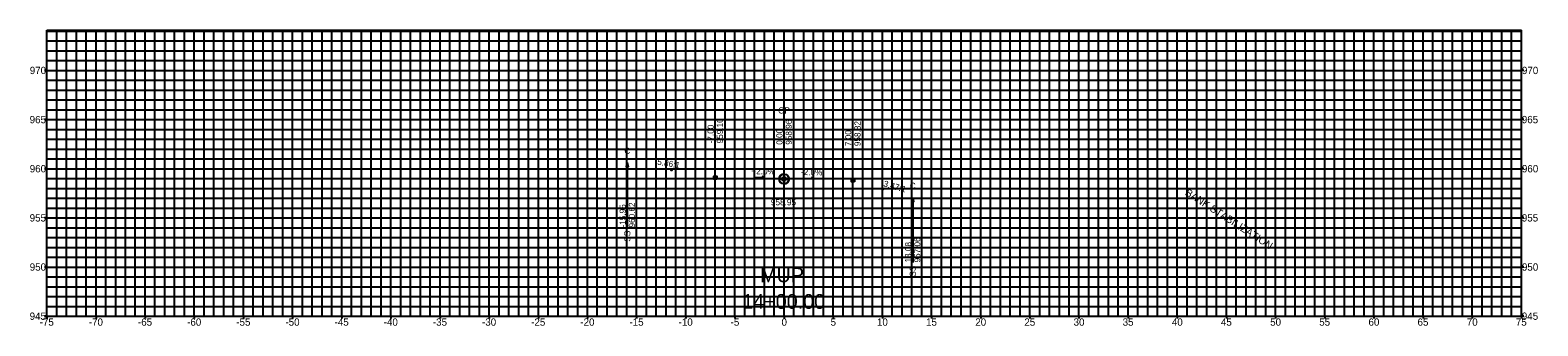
# Model space of a CAD drawing. Extents: x -77 to 77, y 944 to 974.
import ezdxf

# ---------------------------------------------------------------- set-up
doc = ezdxf.new("R2010")
doc.units = 0
for name, color, linetype in [('Default', 7, 'Continuous'), ('E_NCDOT_Terrain_Model_Boundary', 7, 'Continuous'), ('E_NCDOT_Terrain_Model_Breakline', 7, 'Continuous'), ('E_NCDOT_Terrain_Model_Contour_Imported', 7, 'Continuous'), ('E_NCDOT_Terrain_Model_Flow_Arrows', 7, 'Continuous'), ('E_NCDOT_Terrain_Model_Hole', 7, 'Continuous'), ('E_NCDOT_Terrain_Model_Island', 7, 'Continuous'), ('E_NCDOT_Terrain_Model_Points_High', 7, 'Continuous'), ('E_NCDOT_Terrain_Model_Points_Low', 7, 'Continuous'), ('P_NCDOT_XS_Label_Grade_Point', 7, 'Continuous'), ('P_NCDOT_XS_Label_Grading_Side_Slope', 7, 'Continuous'), ('P_NCDOT_XS_Leader_Line', 7, 'Continuous'), ('Prop XS Grade Point', 7, 'Continuous'), ('Prop XS Label Slope Superelevation', 7, 'Continuous')]:
    doc.layers.add(name, color=color, linetype=linetype)

msp = doc.modelspace()

# ---------------------------------------------------------------- linework, layer by layer
at = {"layer": 'Default'}
for p, q in [((-11.47, 959.86), (-11.47, 959.86)), ((10.04, 957.94), (10.04, 957.94))]:
    msp.add_line(p, q, dxfattribs=at)
at = {"layer": 'E_NCDOT_Terrain_Model_Boundary'}
for centre in [(-11.47, 959.86), (10.04, 957.94)]:
    msp.add_circle(centre, 0.05, dxfattribs=at)
at = {"layer": 'E_NCDOT_Terrain_Model_Flow_Arrows'}
for p, q in [((-75, 974.1), (75, 974.1)), ((-75, 945), (-75, 974.1)), ((75, 945), (75, 974.1)), ((-75, 945), (75, 945))]:
    msp.add_line(p, q, dxfattribs=at)
at = {"layer": 'E_NCDOT_Terrain_Model_Hole'}
for p, q in [((-70, 945), (-70, 974.1)), ((-60, 945), (-60, 974.1)), ((-50, 945), (-50, 974.1)), ((-40, 945), (-40, 974.1)), ((-30, 945), (-30, 974.1)), ((-20, 945), (-20, 974.1)), ((-10, 945), (-10, 974.1)), ((0, 945), (0, 974.1)), ((10, 945), (10, 974.1)), ((20, 945), (20, 974.1)), ((30, 945), (30, 974.1)), ((40, 945), (40, 974.1)), ((50, 945), (50, 974.1)), ((60, 945), (60, 974.1)), ((70, 945), (70, 974.1)), ((-75, 970), (75, 970)), ((-75, 960), (75, 960)), ((-75, 950), (75, 950))]:
    msp.add_line(p, q, dxfattribs=at)
at = {"layer": 'E_NCDOT_Terrain_Model_Points_High'}
for p, q in [((-75, 974), (75, 974)), ((-74, 945), (-74, 974.1)), ((-73, 945), (-73, 974.1)), ((-72, 945), (-72, 974.1)), ((-71, 945), (-71, 974.1)), ((-69, 945), (-69, 974.1)), ((-68, 945), (-68, 974.1)), ((-67, 945), (-67, 974.1)), ((-66, 945), (-66, 974.1)), ((-64, 945), (-64, 974.1)), ((-63, 945), (-63, 974.1)), ((-62, 945), (-62, 974.1)), ((-61, 945), (-61, 974.1)), ((-59, 945), (-59, 974.1)), ((-58, 945), (-58, 974.1)), ((-57, 945), (-57, 974.1)), ((-56, 945), (-56, 974.1)), ((-54, 945), (-54, 974.1)), ((-53, 945), (-53, 974.1)), ((-52, 945), (-52, 974.1)), ((-51, 945), (-51, 974.1)), ((-49, 945), (-49, 974.1)), ((-48, 945), (-48, 974.1)), ((-47, 945), (-47, 974.1)), ((-46, 945), (-46, 974.1)), ((-44, 945), (-44, 974.1)), ((-43, 945), (-43, 974.1)), ((-42, 945), (-42, 974.1)), ((-41, 945), (-41, 974.1)), ((-39, 945), (-39, 974.1)), ((-38, 945), (-38, 974.1)), ((-37, 945), (-37, 974.1)), ((-36, 945), (-36, 974.1)), ((-34, 945), (-34, 974.1)), ((-33, 945), (-33, 974.1)), ((-32, 945), (-32, 974.1)), ((-31, 945), (-31, 974.1)), ((-29, 945), (-29, 974.1)), ((-28, 945), (-28, 974.1)), ((-27, 945), (-27, 974.1)), ((-26, 945), (-26, 974.1)), ((-24, 945), (-24, 974.1)), ((-23, 945), (-23, 974.1)), ((-22, 945), (-22, 974.1)), ((-21, 945), (-21, 974.1)), ((-19, 945), (-19, 974.1)), ((-18, 945), (-18, 974.1)), ((-17, 945), (-17, 974.1)), ((-16, 945), (-16, 974.1)), ((-14, 945), (-14, 974.1)), ((-13, 945), (-13, 974.1)), ((-12, 945), (-12, 974.1)), ((-11, 945), (-11, 974.1)), ((-9, 945), (-9, 974.1)), ((-8, 945), (-8, 974.1)), ((-7, 945), (-7, 974.1)), ((-6, 945), (-6, 974.1)), ((-4, 945), (-4, 974.1)), ((-3, 945), (-3, 974.1)), ((-2, 945), (-2, 974.1)), ((-1, 945), (-1, 974.1)), ((1, 945), (1, 974.1)), ((2, 945), (2, 974.1)), ((3, 945), (3, 974.1)), ((4, 945), (4, 974.1)), ((6, 945), (6, 974.1)), ((7, 945), (7, 974.1)), ((8, 945), (8, 974.1)), ((9, 945), (9, 974.1)), ((11, 945), (11, 974.1)), ((12, 945), (12, 974.1)), ((13, 945), (13, 974.1)), ((14, 945), (14, 974.1)), ((16, 945), (16, 974.1)), ((17, 945), (17, 974.1)), ((18, 945), (18, 974.1)), ((19, 945), (19, 974.1)), ((21, 945), (21, 974.1)), ((22, 945), (22, 974.1)), ((23, 945), (23, 974.1)), ((24, 945), (24, 974.1)), ((26, 945), (26, 974.1)), ((27, 945), (27, 974.1)), ((28, 945), (28, 974.1)), ((29, 945), (29, 974.1)), ((31, 945), (31, 974.1)), ((32, 945), (32, 974.1)), ((33, 945), (33, 974.1)), ((34, 945), (34, 974.1)), ((36, 945), (36, 974.1)), ((37, 945), (37, 974.1)), ((38, 945), (38, 974.1)), ((39, 945), (39, 974.1)), ((41, 945), (41, 974.1)), ((42, 945), (42, 974.1)), ((43, 945), (43, 974.1)), ((44, 945), (44, 974.1)), ((46, 945), (46, 974.1)), ((47, 945), (47, 974.1)), ((48, 945), (48, 974.1)), ((49, 945), (49, 974.1)), ((51, 945), (51, 974.1)), ((52, 945), (52, 974.1)), ((53, 945), (53, 974.1)), ((54, 945), (54, 974.1)), ((56, 945), (56, 974.1)), ((57, 945), (57, 974.1)), ((58, 945), (58, 974.1)), ((59, 945), (59, 974.1)), ((61, 945), (61, 974.1)), ((62, 945), (62, 974.1)), ((63, 945), (63, 974.1)), ((64, 945), (64, 974.1)), ((66, 945), (66, 974.1)), ((67, 945), (67, 974.1)), ((68, 945), (68, 974.1)), ((69, 945), (69, 974.1)), ((71, 945), (71, 974.1)), ((72, 945), (72, 974.1)), ((73, 945), (73, 974.1)), ((74, 945), (74, 974.1)), ((-75, 973), (75, 973)), ((-75, 972), (75, 972)), ((-75, 971), (75, 971)), ((-75, 969), (75, 969)), ((-75, 968), (75, 968)), ((-75, 967), (75, 967)), ((-75, 966), (75, 966)), ((-75, 964), (75, 964)), ((-75, 963), (75, 963)), ((-75, 962), (75, 962)), ((-75, 961), (75, 961)), ((-75, 959), (75, 959)), ((-75, 958), (75, 958)), ((-75, 957), (75, 957)), ((-75, 956), (75, 956)), ((-75, 954), (75, 954)), ((-75, 953), (75, 953)), ((-75, 952), (75, 952)), ((-75, 951), (75, 951)), ((-75, 949), (75, 949)), ((-75, 948), (75, 948)), ((-75, 947), (75, 947)), ((-75, 946), (75, 946))]:
    msp.add_line(p, q, dxfattribs=at)
at = {"layer": 'E_NCDOT_Terrain_Model_Points_Low'}
for p, q in [((-70, 945), (-70, 974.1)), ((-65, 945), (-65, 974.1)), ((-60, 945), (-60, 974.1)), ((-55, 945), (-55, 974.1)), ((-50, 945), (-50, 974.1)), ((-45, 945), (-45, 974.1)), ((-40, 945), (-40, 974.1)), ((-35, 945), (-35, 974.1)), ((-30, 945), (-30, 974.1)), ((-25, 945), (-25, 974.1)), ((-20, 945), (-20, 974.1)), ((-15, 945), (-15, 974.1)), ((-10, 945), (-10, 974.1)), ((-5, 945), (-5, 974.1)), ((0, 945), (0, 974.1)), ((5, 945), (5, 974.1)), ((10, 945), (10, 974.1)), ((15, 945), (15, 974.1)), ((20, 945), (20, 974.1)), ((25, 945), (25, 974.1)), ((30, 945), (30, 974.1)), ((35, 945), (35, 974.1)), ((40, 945), (40, 974.1)), ((45, 945), (45, 974.1)), ((50, 945), (50, 974.1)), ((55, 945), (55, 974.1)), ((60, 945), (60, 974.1)), ((65, 945), (65, 974.1)), ((70, 945), (70, 974.1)), ((-75, 970), (-75.24, 970)), ((-75, 970), (75, 970)), ((75.24, 970), (75, 970)), ((-75, 965), (-75.24, 965)), ((-75, 965), (75, 965)), ((75.24, 965), (75, 965)), ((-75, 960), (-75.24, 960)), ((-75, 960), (75, 960)), ((75.24, 960), (75, 960)), ((-75, 955), (-75.24, 955)), ((-75, 955), (75, 955)), ((75.24, 955), (75, 955)), ((-75, 950), (-75.24, 950)), ((-75, 950), (75, 950)), ((75.24, 950), (75, 950)), ((-75, 945), (-75.24, 945)), ((-75, 945), (-75, 944.76)), ((-70, 945), (-70, 944.76)), ((-65, 945), (-65, 944.76)), ((-60, 945), (-60, 944.76)), ((-55, 945), (-55, 944.76)), ((-50, 945), (-50, 944.76)), ((-45, 945), (-45, 944.76)), ((-40, 945), (-40, 944.76)), ((-35, 945), (-35, 944.76)), ((-30, 945), (-30, 944.76)), ((-25, 945), (-25, 944.76)), ((-20, 945), (-20, 944.76)), ((-15, 945), (-15, 944.76)), ((-10, 945), (-10, 944.76)), ((-5, 945), (-5, 944.76)), ((0, 945), (0, 944.76)), ((5, 945), (5, 944.76)), ((10, 945), (10, 944.76)), ((15, 945), (15, 944.76)), ((20, 945), (20, 944.76)), ((25, 945), (25, 944.76)), ((30, 945), (30, 944.76)), ((35, 945), (35, 944.76)), ((40, 945), (40, 944.76)), ((45, 945), (45, 944.76)), ((50, 945), (50, 944.76)), ((55, 945), (55, 944.76)), ((60, 945), (60, 944.76)), ((65, 945), (65, 944.76)), ((70, 945), (70, 944.76)), ((75, 945), (75, 944.76)), ((75.24, 945), (75, 945))]:
    msp.add_line(p, q, dxfattribs=at)
at = {"layer": 'P_NCDOT_XS_Leader_Line'}
for p, q in [((-7, 959.1), (-7, 965.34)), ((0, 958.96), (0, 965.2)), ((7, 958.82), (7, 965.06)), ((-15.95, 960.62), (-15.95, 954.02)), ((13.08, 957.06), (13.08, 950.46))]:
    msp.add_line(p, q, dxfattribs=at)
for points in [[(-15.95, 960.62), (-15.86, 960.21), (-16.04, 960.21)], [(-6.85, 958.95), (-7.15, 958.95), (-7.15, 959.25), (-6.85, 959.25)], [(0.15, 958.81), (-0.15, 958.81), (-0.15, 959.11), (0.15, 959.11)], [(7.15, 958.67), (6.85, 958.67), (6.85, 958.97), (7.15, 958.97)], [(13.08, 957.06), (13.17, 956.65), (13, 956.65)]]:
    msp.add_lwpolyline(points, close=True, dxfattribs=at)
at = {"layer": 'Prop XS Grade Point'}
for p, q in [((-0.5, 958.96), (0.5, 958.96)), ((0, 959.46), (0, 958.46))]:
    msp.add_line(p, q, dxfattribs=at)
for points in [[(-0.5, 958.96), (0, 958.96), (0, 959.46)], [(0.5, 958.96), (0, 958.96), (0, 958.46)]]:
    msp.add_lwpolyline(points, dxfattribs=at)
msp.add_circle((0, 958.96), 0.5, dxfattribs=at)
for start, end in [(90, 180), (270, 0)]:
    msp.add_arc((0, 958.96), 0.5, start, end, dxfattribs=at)
at = {"layer": 'Prop XS Label Slope Superelevation'}
for p, q in [((-2.95, 959.14), (-2.05, 959.12)), ((-2.05, 959.12), (-2.22, 959.24)), ((2.05, 959.04), (2.95, 959.02)), ((2.95, 959.02), (2.78, 959.14))]:
    msp.add_line(p, q, dxfattribs=at)

# ---------------------------------------------------------------- texts
at = {"layer": 'E_NCDOT_Terrain_Model_Breakline'}
for s, p in [('MUP', (-2.44, 948.45)), ('14+00.00', (-4.25, 945.75))]:
    msp.add_text(s, height=1.5, dxfattribs=at).set_placement(p)
at = {"layer": 'E_NCDOT_Terrain_Model_Contour_Imported'}
for s, height, rotation, p in [('5.86:1', 0.624, 350.3163, (-12.94, 960.42)), ('+2.0%', 0.624, 358.8542, (-3.33, 959.46)), ('-2.0%', 0.624, 358.8542, (1.71, 959.36)), ('3.47:1', 0.624, 343.9098, (10.06, 958.22)), ('BANK STABILIZATION', 0.744, 327.0375, (40.73, 957.39))]:
    msp.add_text(s, height=height, rotation=rotation, dxfattribs=at).set_placement(p)
msp.add_text('958.95', height=0.624, dxfattribs=at).set_placement((-1.34, 956.28))
at = {"layer": 'E_NCDOT_Terrain_Model_Island'}
for s, p in [('970', (-76.74, 969.63)), ('970', (75.06, 969.63)), ('965', (-76.75, 964.63)), ('965', (75.05, 964.63)), ('960', (-76.74, 959.63)), ('960', (75.06, 959.63)), ('955', (-76.75, 954.63)), ('955', (75.05, 954.63)), ('950', (-76.74, 949.63)), ('950', (75.06, 949.63)), ('945', (-76.75, 944.63)), ('945', (75.05, 944.63)), ('-75', (-75.73, 944.03)), ('-70', (-70.73, 944.03)), ('-65', (-65.73, 944.03)), ('-60', (-60.73, 944.03)), ('-55', (-55.73, 944.03)), ('-50', (-50.73, 944.03)), ('-45', (-45.73, 944.03)), ('-40', (-40.73, 944.03)), ('-35', (-35.73, 944.03)), ('-30', (-30.73, 944.03)), ('-25', (-25.73, 944.03)), ('-20', (-20.73, 944.03)), ('-15', (-15.73, 944.03)), ('-10', (-10.73, 944.03)), ('-5', (-5.44, 944.03)), ('0', (-0.26, 944.03)), ('5', (4.73, 944.03)), ('10', (9.45, 944.03)), ('15', (14.44, 944.03)), ('20', (19.45, 944.03)), ('25', (24.44, 944.03)), ('30', (29.45, 944.03)), ('35', (34.44, 944.03)), ('40', (39.45, 944.03)), ('45', (44.44, 944.03)), ('50', (49.45, 944.03)), ('55', (54.44, 944.03)), ('60', (59.45, 944.03)), ('65', (64.44, 944.03)), ('70', (69.45, 944.03)), ('75', (74.44, 944.03))]:
    msp.add_text(s, height=0.744, dxfattribs=at).set_placement(p)
at = {"layer": 'P_NCDOT_XS_Label_Grade_Point'}
for s, p in [('959.10', (-6.22, 962.58)), ('958.96', (0.78, 962.44)), ('958.82', (7.78, 962.3)), ('-7.00', (-7.16, 962.58)), ('0.00', (-0.16, 962.44)), ('7.00', (6.84, 962.3))]:
    msp.add_text(s, height=0.624, rotation=90, dxfattribs=at).set_placement(p)
msp.add_text('GP', height=0.624, dxfattribs=at).set_placement((-0.61, 965.62))
at = {"layer": 'P_NCDOT_XS_Label_Grading_Side_Slope'}
for p in [(-16.25, 961.51), (12.78, 957.95)]:
    msp.add_text('C', height=0.624, dxfattribs=at).set_placement(p)
for s, p in [('-15.95', (-16.11, 954.02)), ('960.62', (-15.17, 954.02)), ('SS', (-15.64, 952.58)), ('13.08', (12.93, 950.46)), ('957.06', (13.86, 950.46)), ('SS', (13.4, 949.02))]:
    msp.add_text(s, height=0.624, rotation=90, dxfattribs=at).set_placement(p)

doc.saveas('drawing.dxf')
